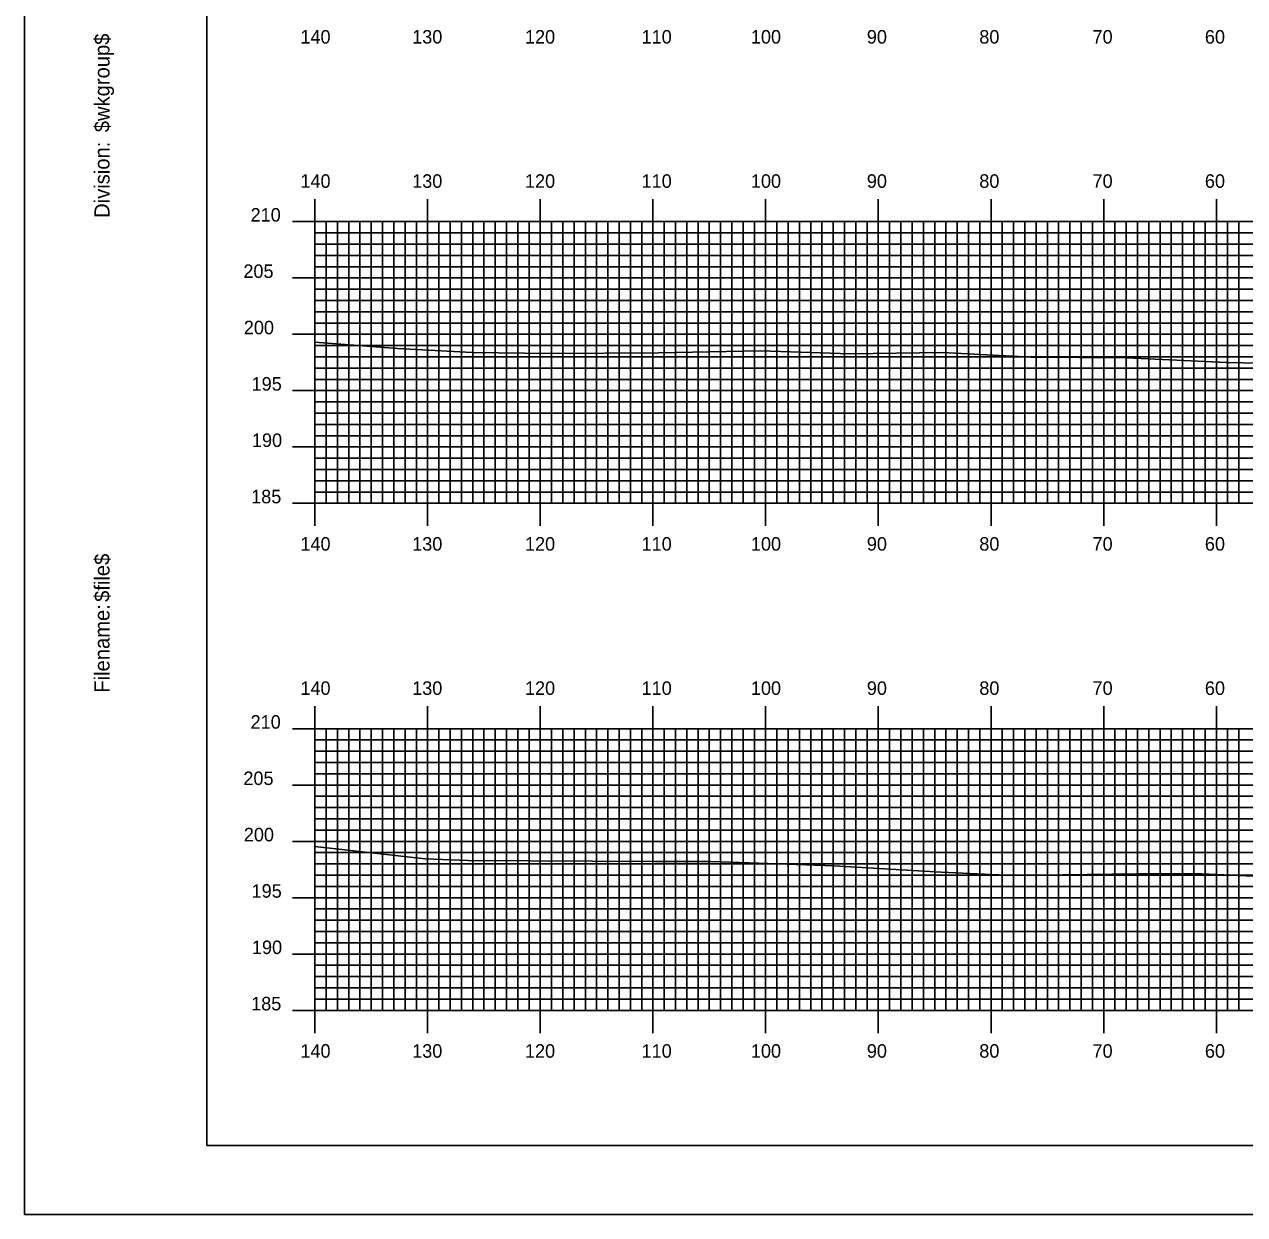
# Model space of a CAD drawing. Extents: x 1814128 to 1814471, y 442591 to 442811.
# Drawn here: x 1814128.2 to 1814236.5, y 442590.5 to 442696.2 of the extents above; entities that cross this region are included whole.
import ezdxf

# ---------------------------------------------------------------- set-up
doc = ezdxf.new("R2010")
doc.units = 0
for name, color, linetype in [('BORDER', 7, 'Continuous'), ('H_V ANNOTATION', 7, 'Continuous'), ('MAJOR', 7, 'Continuous'), ('MINOR', 7, 'Continuous'), ('PLOT BOUNDARY', 7, 'Continuous'), ('S_Roadway_Centerline', 7, 'Continuous')]:
    doc.layers.add(name, color=color, linetype=linetype)

msp = doc.modelspace()

# ---------------------------------------------------------------- linework, layer by layer
at = {"layer": 'BORDER'}
msp.add_lwpolyline([(1814144.39, 442596.67), (1814464.39, 442596.67), (1814464.39, 442806.67), (1814144.39, 442806.67)], close=True, dxfattribs=at)
at = {"layer": 'MAJOR'}
for p, q in [((1814153.99, 442680.67), (1814153.99, 442678.67)), ((1814163.99, 442680.67), (1814163.99, 442678.67)), ((1814173.99, 442680.67), (1814173.99, 442678.67)), ((1814183.99, 442680.67), (1814183.99, 442678.67)), ((1814193.99, 442680.67), (1814193.99, 442678.67)), ((1814203.99, 442680.67), (1814203.99, 442678.67)), ((1814213.99, 442680.67), (1814213.99, 442678.67)), ((1814223.99, 442680.67), (1814223.99, 442678.67)), ((1814233.99, 442680.67), (1814233.99, 442678.67)), ((1814151.99, 442678.67), (1814153.99, 442678.67)), ((1814153.99, 442678.67), (1814433.99, 442678.67)), ((1814153.99, 442653.67), (1814153.99, 442678.67)), ((1814153.99, 442653.67), (1814153.99, 442678.67)), ((1814153.99, 442678.67), (1814433.99, 442678.67)), ((1814163.99, 442653.67), (1814163.99, 442678.67)), ((1814173.99, 442653.67), (1814173.99, 442678.67)), ((1814183.99, 442653.67), (1814183.99, 442678.67)), ((1814193.99, 442653.67), (1814193.99, 442678.67)), ((1814203.99, 442653.67), (1814203.99, 442678.67)), ((1814213.99, 442653.67), (1814213.99, 442678.67)), ((1814223.99, 442653.67), (1814223.99, 442678.67)), ((1814233.99, 442653.67), (1814233.99, 442678.67)), ((1814151.99, 442673.67), (1814153.99, 442673.67)), ((1814153.99, 442673.67), (1814433.99, 442673.67)), ((1814151.99, 442668.67), (1814153.99, 442668.67)), ((1814153.99, 442668.67), (1814433.99, 442668.67)), ((1814151.99, 442663.67), (1814153.99, 442663.67)), ((1814153.99, 442663.67), (1814433.99, 442663.67)), ((1814151.99, 442658.67), (1814153.99, 442658.67)), ((1814153.99, 442658.67), (1814433.99, 442658.67)), ((1814151.99, 442653.67), (1814153.99, 442653.67)), ((1814153.99, 442653.67), (1814433.99, 442653.67)), ((1814153.99, 442653.67), (1814433.99, 442653.67)), ((1814153.99, 442651.66), (1814153.99, 442653.67)), ((1814163.99, 442651.66), (1814163.99, 442653.67)), ((1814173.99, 442651.66), (1814173.99, 442653.67)), ((1814183.99, 442651.66), (1814183.99, 442653.67)), ((1814193.99, 442651.66), (1814193.99, 442653.67)), ((1814203.99, 442651.66), (1814203.99, 442653.67)), ((1814213.99, 442651.66), (1814213.99, 442653.67)), ((1814223.99, 442651.66), (1814223.99, 442653.67)), ((1814233.99, 442651.66), (1814233.99, 442653.67)), ((1814153.99, 442635.67), (1814153.99, 442633.67)), ((1814163.99, 442635.67), (1814163.99, 442633.67)), ((1814173.99, 442635.67), (1814173.99, 442633.67)), ((1814183.99, 442635.67), (1814183.99, 442633.67)), ((1814193.99, 442635.67), (1814193.99, 442633.67)), ((1814203.99, 442635.67), (1814203.99, 442633.67)), ((1814213.99, 442635.67), (1814213.99, 442633.67)), ((1814223.99, 442635.67), (1814223.99, 442633.67)), ((1814233.99, 442635.67), (1814233.99, 442633.67)), ((1814151.99, 442633.67), (1814153.99, 442633.67)), ((1814153.99, 442633.67), (1814433.99, 442633.67)), ((1814153.99, 442608.67), (1814153.99, 442633.67)), ((1814153.99, 442608.67), (1814153.99, 442633.67)), ((1814153.99, 442633.67), (1814433.99, 442633.67)), ((1814163.99, 442608.67), (1814163.99, 442633.67)), ((1814173.99, 442608.67), (1814173.99, 442633.67)), ((1814183.99, 442608.67), (1814183.99, 442633.67)), ((1814193.99, 442608.67), (1814193.99, 442633.67)), ((1814203.99, 442608.67), (1814203.99, 442633.67)), ((1814213.99, 442608.67), (1814213.99, 442633.67)), ((1814223.99, 442608.67), (1814223.99, 442633.67)), ((1814233.99, 442608.67), (1814233.99, 442633.67)), ((1814151.99, 442628.67), (1814153.99, 442628.67)), ((1814153.99, 442628.67), (1814433.99, 442628.67)), ((1814151.99, 442623.67), (1814153.99, 442623.67)), ((1814153.99, 442623.67), (1814433.99, 442623.67)), ((1814151.99, 442618.67), (1814153.99, 442618.67)), ((1814153.99, 442618.67), (1814433.99, 442618.67)), ((1814151.99, 442613.67), (1814153.99, 442613.67)), ((1814153.99, 442613.67), (1814433.99, 442613.67)), ((1814151.99, 442608.67), (1814153.99, 442608.67)), ((1814153.99, 442608.67), (1814433.99, 442608.67)), ((1814153.99, 442608.67), (1814433.99, 442608.67)), ((1814153.99, 442606.66), (1814153.99, 442608.67)), ((1814163.99, 442606.66), (1814163.99, 442608.67)), ((1814173.99, 442606.66), (1814173.99, 442608.67)), ((1814183.99, 442606.66), (1814183.99, 442608.67)), ((1814193.99, 442606.66), (1814193.99, 442608.67)), ((1814203.99, 442606.66), (1814203.99, 442608.67)), ((1814213.99, 442606.66), (1814213.99, 442608.67)), ((1814223.99, 442606.66), (1814223.99, 442608.67)), ((1814233.99, 442606.66), (1814233.99, 442608.67))]:
    msp.add_line(p, q, dxfattribs=at)
at = {"layer": 'MINOR'}
for p, q in [((1814154.99, 442653.67), (1814154.99, 442678.67)), ((1814155.99, 442653.67), (1814155.99, 442678.67)), ((1814156.99, 442653.67), (1814156.99, 442678.67)), ((1814157.99, 442653.67), (1814157.99, 442678.67)), ((1814158.99, 442653.67), (1814158.99, 442678.67)), ((1814159.99, 442653.67), (1814159.99, 442678.67)), ((1814160.99, 442653.67), (1814160.99, 442678.67)), ((1814161.99, 442653.67), (1814161.99, 442678.67)), ((1814162.99, 442653.67), (1814162.99, 442678.67)), ((1814164.99, 442653.67), (1814164.99, 442678.67)), ((1814165.99, 442653.67), (1814165.99, 442678.67)), ((1814166.99, 442653.67), (1814166.99, 442678.67)), ((1814167.99, 442653.67), (1814167.99, 442678.67)), ((1814168.99, 442653.67), (1814168.99, 442678.67)), ((1814169.99, 442653.67), (1814169.99, 442678.67)), ((1814170.99, 442653.67), (1814170.99, 442678.67)), ((1814171.99, 442653.67), (1814171.99, 442678.67)), ((1814172.99, 442653.67), (1814172.99, 442678.67)), ((1814174.99, 442653.67), (1814174.99, 442678.67)), ((1814175.99, 442653.67), (1814175.99, 442678.67)), ((1814176.99, 442653.67), (1814176.99, 442678.67)), ((1814177.99, 442653.67), (1814177.99, 442678.67)), ((1814178.99, 442653.67), (1814178.99, 442678.67)), ((1814179.99, 442653.67), (1814179.99, 442678.67)), ((1814180.99, 442653.67), (1814180.99, 442678.67)), ((1814181.99, 442653.67), (1814181.99, 442678.67)), ((1814182.99, 442653.67), (1814182.99, 442678.67)), ((1814184.99, 442653.67), (1814184.99, 442678.67)), ((1814185.99, 442653.67), (1814185.99, 442678.67)), ((1814186.99, 442653.67), (1814186.99, 442678.67)), ((1814187.99, 442653.67), (1814187.99, 442678.67)), ((1814188.99, 442653.67), (1814188.99, 442678.67)), ((1814189.99, 442653.67), (1814189.99, 442678.67)), ((1814190.99, 442653.67), (1814190.99, 442678.67)), ((1814191.99, 442653.67), (1814191.99, 442678.67)), ((1814192.99, 442653.67), (1814192.99, 442678.67)), ((1814194.99, 442653.67), (1814194.99, 442678.67)), ((1814195.99, 442653.67), (1814195.99, 442678.67)), ((1814196.99, 442653.67), (1814196.99, 442678.67)), ((1814197.99, 442653.67), (1814197.99, 442678.67)), ((1814198.99, 442653.67), (1814198.99, 442678.67)), ((1814199.99, 442653.67), (1814199.99, 442678.67)), ((1814200.99, 442653.67), (1814200.99, 442678.67)), ((1814201.99, 442653.67), (1814201.99, 442678.67)), ((1814202.99, 442653.67), (1814202.99, 442678.67)), ((1814204.99, 442653.67), (1814204.99, 442678.67)), ((1814205.99, 442653.67), (1814205.99, 442678.67)), ((1814206.99, 442653.67), (1814206.99, 442678.67)), ((1814207.99, 442653.67), (1814207.99, 442678.67)), ((1814208.99, 442653.67), (1814208.99, 442678.67)), ((1814209.99, 442653.67), (1814209.99, 442678.67)), ((1814210.99, 442653.67), (1814210.99, 442678.67)), ((1814211.99, 442653.67), (1814211.99, 442678.67)), ((1814212.99, 442653.67), (1814212.99, 442678.67)), ((1814214.99, 442653.67), (1814214.99, 442678.67)), ((1814215.99, 442653.67), (1814215.99, 442678.67)), ((1814216.99, 442653.67), (1814216.99, 442678.67)), ((1814217.99, 442653.67), (1814217.99, 442678.67)), ((1814218.99, 442653.67), (1814218.99, 442678.67)), ((1814219.99, 442653.67), (1814219.99, 442678.67)), ((1814220.99, 442653.67), (1814220.99, 442678.67)), ((1814221.99, 442653.67), (1814221.99, 442678.67)), ((1814222.99, 442653.67), (1814222.99, 442678.67)), ((1814224.99, 442653.67), (1814224.99, 442678.67)), ((1814225.99, 442653.67), (1814225.99, 442678.67)), ((1814226.99, 442653.67), (1814226.99, 442678.67)), ((1814227.99, 442653.67), (1814227.99, 442678.67)), ((1814228.99, 442653.67), (1814228.99, 442678.67)), ((1814229.99, 442653.67), (1814229.99, 442678.67)), ((1814230.99, 442653.67), (1814230.99, 442678.67)), ((1814231.99, 442653.67), (1814231.99, 442678.67)), ((1814232.99, 442653.67), (1814232.99, 442678.67)), ((1814234.99, 442653.67), (1814234.99, 442678.67)), ((1814235.99, 442653.67), (1814235.99, 442678.67)), ((1814153.99, 442677.67), (1814433.99, 442677.67)), ((1814153.99, 442677.67), (1814156, 442677.67)), ((1814153.99, 442676.67), (1814433.99, 442676.67)), ((1814153.99, 442676.67), (1814156, 442676.67)), ((1814153.99, 442675.67), (1814433.99, 442675.67)), ((1814153.99, 442675.67), (1814156, 442675.67)), ((1814153.99, 442674.67), (1814433.99, 442674.67)), ((1814153.99, 442674.67), (1814156, 442674.67)), ((1814153.99, 442672.67), (1814433.99, 442672.67)), ((1814153.99, 442672.67), (1814156, 442672.67)), ((1814153.99, 442671.67), (1814433.99, 442671.67)), ((1814153.99, 442671.67), (1814156, 442671.67)), ((1814153.99, 442670.67), (1814433.99, 442670.67)), ((1814153.99, 442670.67), (1814156, 442670.67)), ((1814153.99, 442669.67), (1814433.99, 442669.67)), ((1814153.99, 442669.67), (1814156, 442669.67)), ((1814153.99, 442667.67), (1814433.99, 442667.67)), ((1814153.99, 442667.67), (1814156, 442667.67)), ((1814153.99, 442666.67), (1814433.99, 442666.67)), ((1814153.99, 442666.67), (1814156, 442666.67)), ((1814153.99, 442665.67), (1814433.99, 442665.67)), ((1814153.99, 442665.67), (1814156, 442665.67)), ((1814153.99, 442664.67), (1814433.99, 442664.67)), ((1814153.99, 442664.67), (1814156, 442664.67)), ((1814153.99, 442662.67), (1814433.99, 442662.67)), ((1814153.99, 442662.67), (1814156, 442662.67)), ((1814153.99, 442661.67), (1814433.99, 442661.67)), ((1814153.99, 442661.67), (1814156, 442661.67)), ((1814153.99, 442660.67), (1814433.99, 442660.67)), ((1814153.99, 442660.67), (1814156, 442660.67)), ((1814153.99, 442659.67), (1814433.99, 442659.67)), ((1814153.99, 442659.67), (1814156, 442659.67)), ((1814153.99, 442657.67), (1814433.99, 442657.67)), ((1814153.99, 442657.67), (1814156, 442657.67)), ((1814153.99, 442656.67), (1814433.99, 442656.67)), ((1814153.99, 442656.67), (1814156, 442656.67)), ((1814153.99, 442655.67), (1814433.99, 442655.67)), ((1814153.99, 442655.67), (1814156, 442655.67)), ((1814153.99, 442654.67), (1814433.99, 442654.67)), ((1814153.99, 442654.67), (1814156, 442654.67)), ((1814154.99, 442608.67), (1814154.99, 442633.67)), ((1814155.99, 442608.67), (1814155.99, 442633.67)), ((1814156.99, 442608.67), (1814156.99, 442633.67)), ((1814157.99, 442608.67), (1814157.99, 442633.67)), ((1814158.99, 442608.67), (1814158.99, 442633.67)), ((1814159.99, 442608.67), (1814159.99, 442633.67)), ((1814160.99, 442608.67), (1814160.99, 442633.67)), ((1814161.99, 442608.67), (1814161.99, 442633.67)), ((1814162.99, 442608.67), (1814162.99, 442633.67)), ((1814164.99, 442608.67), (1814164.99, 442633.67)), ((1814165.99, 442608.67), (1814165.99, 442633.67)), ((1814166.99, 442608.67), (1814166.99, 442633.67)), ((1814167.99, 442608.67), (1814167.99, 442633.67)), ((1814168.99, 442608.67), (1814168.99, 442633.67)), ((1814169.99, 442608.67), (1814169.99, 442633.67)), ((1814170.99, 442608.67), (1814170.99, 442633.67)), ((1814171.99, 442608.67), (1814171.99, 442633.67)), ((1814172.99, 442608.67), (1814172.99, 442633.67)), ((1814174.99, 442608.67), (1814174.99, 442633.67)), ((1814175.99, 442608.67), (1814175.99, 442633.67)), ((1814176.99, 442608.67), (1814176.99, 442633.67)), ((1814177.99, 442608.67), (1814177.99, 442633.67)), ((1814178.99, 442608.67), (1814178.99, 442633.67)), ((1814179.99, 442608.67), (1814179.99, 442633.67)), ((1814180.99, 442608.67), (1814180.99, 442633.67)), ((1814181.99, 442608.67), (1814181.99, 442633.67)), ((1814182.99, 442608.67), (1814182.99, 442633.67)), ((1814184.99, 442608.67), (1814184.99, 442633.67)), ((1814185.99, 442608.67), (1814185.99, 442633.67)), ((1814186.99, 442608.67), (1814186.99, 442633.67)), ((1814187.99, 442608.67), (1814187.99, 442633.67)), ((1814188.99, 442608.67), (1814188.99, 442633.67)), ((1814189.99, 442608.67), (1814189.99, 442633.67)), ((1814190.99, 442608.67), (1814190.99, 442633.67)), ((1814191.99, 442608.67), (1814191.99, 442633.67)), ((1814192.99, 442608.67), (1814192.99, 442633.67)), ((1814194.99, 442608.67), (1814194.99, 442633.67)), ((1814195.99, 442608.67), (1814195.99, 442633.67)), ((1814196.99, 442608.67), (1814196.99, 442633.67)), ((1814197.99, 442608.67), (1814197.99, 442633.67)), ((1814198.99, 442608.67), (1814198.99, 442633.67)), ((1814199.99, 442608.67), (1814199.99, 442633.67)), ((1814200.99, 442608.67), (1814200.99, 442633.67)), ((1814201.99, 442608.67), (1814201.99, 442633.67)), ((1814202.99, 442608.67), (1814202.99, 442633.67)), ((1814204.99, 442608.67), (1814204.99, 442633.67)), ((1814205.99, 442608.67), (1814205.99, 442633.67)), ((1814206.99, 442608.67), (1814206.99, 442633.67)), ((1814207.99, 442608.67), (1814207.99, 442633.67)), ((1814208.99, 442608.67), (1814208.99, 442633.67)), ((1814209.99, 442608.67), (1814209.99, 442633.67)), ((1814210.99, 442608.67), (1814210.99, 442633.67)), ((1814211.99, 442608.67), (1814211.99, 442633.67)), ((1814212.99, 442608.67), (1814212.99, 442633.67)), ((1814214.99, 442608.67), (1814214.99, 442633.67)), ((1814215.99, 442608.67), (1814215.99, 442633.67)), ((1814216.99, 442608.67), (1814216.99, 442633.67)), ((1814217.99, 442608.67), (1814217.99, 442633.67)), ((1814218.99, 442608.67), (1814218.99, 442633.67)), ((1814219.99, 442608.67), (1814219.99, 442633.67)), ((1814220.99, 442608.67), (1814220.99, 442633.67)), ((1814221.99, 442608.67), (1814221.99, 442633.67)), ((1814222.99, 442608.67), (1814222.99, 442633.67)), ((1814224.99, 442608.67), (1814224.99, 442633.67)), ((1814225.99, 442608.67), (1814225.99, 442633.67)), ((1814226.99, 442608.67), (1814226.99, 442633.67)), ((1814227.99, 442608.67), (1814227.99, 442633.67)), ((1814228.99, 442608.67), (1814228.99, 442633.67)), ((1814229.99, 442608.67), (1814229.99, 442633.67)), ((1814230.99, 442608.67), (1814230.99, 442633.67)), ((1814231.99, 442608.67), (1814231.99, 442633.67)), ((1814232.99, 442608.67), (1814232.99, 442633.67)), ((1814234.99, 442608.67), (1814234.99, 442633.67)), ((1814235.99, 442608.67), (1814235.99, 442633.67)), ((1814153.99, 442632.67), (1814433.99, 442632.67)), ((1814153.99, 442632.67), (1814156, 442632.67)), ((1814153.99, 442631.67), (1814433.99, 442631.67)), ((1814153.99, 442631.67), (1814156, 442631.67)), ((1814153.99, 442630.67), (1814433.99, 442630.67)), ((1814153.99, 442630.67), (1814156, 442630.67)), ((1814153.99, 442629.67), (1814433.99, 442629.67)), ((1814153.99, 442629.67), (1814156, 442629.67)), ((1814153.99, 442627.67), (1814433.99, 442627.67)), ((1814153.99, 442627.67), (1814156, 442627.67)), ((1814153.99, 442626.67), (1814433.99, 442626.67)), ((1814153.99, 442626.67), (1814156, 442626.67)), ((1814153.99, 442625.67), (1814433.99, 442625.67)), ((1814153.99, 442625.67), (1814156, 442625.67)), ((1814153.99, 442624.67), (1814433.99, 442624.67)), ((1814153.99, 442624.67), (1814156, 442624.67)), ((1814153.99, 442622.67), (1814433.99, 442622.67)), ((1814153.99, 442622.67), (1814156, 442622.67)), ((1814153.99, 442621.67), (1814433.99, 442621.67)), ((1814153.99, 442621.67), (1814156, 442621.67)), ((1814153.99, 442620.67), (1814433.99, 442620.67)), ((1814153.99, 442620.67), (1814156, 442620.67)), ((1814153.99, 442619.67), (1814433.99, 442619.67)), ((1814153.99, 442619.67), (1814156, 442619.67)), ((1814153.99, 442617.67), (1814433.99, 442617.67)), ((1814153.99, 442617.67), (1814156, 442617.67)), ((1814153.99, 442616.67), (1814433.99, 442616.67)), ((1814153.99, 442616.67), (1814156, 442616.67)), ((1814153.99, 442615.67), (1814433.99, 442615.67)), ((1814153.99, 442615.67), (1814156, 442615.67)), ((1814153.99, 442614.67), (1814433.99, 442614.67)), ((1814153.99, 442614.67), (1814156, 442614.67)), ((1814153.99, 442612.67), (1814433.99, 442612.67)), ((1814153.99, 442612.67), (1814156, 442612.67)), ((1814153.99, 442611.67), (1814433.99, 442611.67)), ((1814153.99, 442611.67), (1814156, 442611.67)), ((1814153.99, 442610.67), (1814433.99, 442610.67)), ((1814153.99, 442610.67), (1814156, 442610.67)), ((1814153.99, 442609.67), (1814433.99, 442609.67)), ((1814153.99, 442609.67), (1814156, 442609.67))]:
    msp.add_line(p, q, dxfattribs=at)
at = {"layer": 'PLOT BOUNDARY'}
msp.add_lwpolyline([(1814128.21, 442590.55), (1814468.21, 442590.55), (1814468.21, 442810.55), (1814128.21, 442810.55)], close=True, dxfattribs=at)
at = {"layer": 'S_Roadway_Centerline'}
for points in [[(1814153.99, 442667.97), (1814161.32, 442667.4), (1814167.95, 442667.05), (1814174.94, 442666.98), (1814184.48, 442667.03), (1814193.54, 442667.21), (1814201.48, 442666.94), (1814209.68, 442667.06), (1814217.54, 442666.63), (1814226.05, 442666.58), (1814234.88, 442666.16), (1814242.26, 442666.03), (1814250.37, 442665.6), (1814258.58, 442665.06), (1814275.22, 442664.27), (1814283.53, 442663.9), (1814291.88, 442664.37), (1814299.32, 442663.86), (1814308.93, 442663), (1814316.73, 442662.86), (1814325.57, 442662.36), (1814332.4, 442662.3), (1814342.63, 442662.38), (1814356.37, 442661.7)], [(1814153.99, 442623.21), (1814163.78, 442622.13), (1814167.6, 442621.98), (1814184.17, 442621.87), (1814189.15, 442621.88), (1814200.08, 442621.51), (1814209.56, 442620.94), (1814215.95, 442620.64), (1814226.91, 442620.8), (1814232.69, 442620.8), (1814239.23, 442620.49), (1814249.37, 442620.39), (1814258.43, 442619.91), (1814265.29, 442619.76), (1814273.95, 442619.48), (1814282.83, 442619.21), (1814297.29, 442618.7), (1814314.23, 442618.05), (1814320.92, 442617.59), (1814330.34, 442617.05), (1814337.24, 442616.72), (1814347.7, 442616.32)]]:
    msp.add_lwpolyline(points, dxfattribs=at)

# ---------------------------------------------------------------- texts
at = {"layer": 'BORDER'}
for s, p in [('$wkgroup$', (1814135.76, 442686.6)), ('Division:', (1814135.76, 442679)), ('$file$', (1814135.76, 442644.92)), ('Filename:', (1814135.76, 442636.86))]:
    msp.add_text(s, height=1.339, rotation=90, dxfattribs=at).set_placement(p)
at = {"layer": 'H_V ANNOTATION'}
for s, p in [('140', (1814152.7, 442694.47)), ('130', (1814162.62, 442694.47)), ('120', (1814172.63, 442694.47)), ('110', (1814182.98, 442694.47)), ('100', (1814192.68, 442694.47)), ('90', (1814202.97, 442694.47)), ('80', (1814212.95, 442694.47)), ('70', (1814223, 442694.47)), ('60', (1814232.97, 442694.47)), ('140', (1814152.7, 442681.67)), ('130', (1814162.62, 442681.67)), ('120', (1814172.63, 442681.67)), ('110', (1814182.98, 442681.67)), ('100', (1814192.68, 442681.67)), ('90', (1814202.97, 442681.67)), ('80', (1814212.95, 442681.67)), ('70', (1814223, 442681.67)), ('60', (1814232.97, 442681.67)), ('210', (1814148.28, 442678.67)), ('205', (1814147.64, 442673.67)), ('200', (1814147.68, 442668.67)), ('195', (1814148.37, 442663.67)), ('190', (1814148.4, 442658.67)), ('185', (1814148.33, 442653.67)), ('140', (1814152.7, 442649.47)), ('130', (1814162.62, 442649.47)), ('120', (1814172.63, 442649.47)), ('110', (1814182.98, 442649.47)), ('100', (1814192.68, 442649.47)), ('90', (1814202.97, 442649.47)), ('80', (1814212.95, 442649.47)), ('70', (1814223, 442649.47)), ('60', (1814232.97, 442649.47)), ('140', (1814152.7, 442636.67)), ('130', (1814162.62, 442636.67)), ('120', (1814172.63, 442636.67)), ('110', (1814182.98, 442636.67)), ('100', (1814192.68, 442636.67)), ('90', (1814202.97, 442636.67)), ('80', (1814212.95, 442636.67)), ('70', (1814223, 442636.67)), ('60', (1814232.97, 442636.67)), ('210', (1814148.28, 442633.67)), ('205', (1814147.64, 442628.67)), ('200', (1814147.68, 442623.67)), ('195', (1814148.37, 442618.67)), ('190', (1814148.4, 442613.67)), ('185', (1814148.33, 442608.67)), ('140', (1814152.7, 442604.47)), ('130', (1814162.62, 442604.47)), ('120', (1814172.63, 442604.47)), ('110', (1814182.98, 442604.47)), ('100', (1814192.68, 442604.47)), ('90', (1814202.97, 442604.47)), ('80', (1814212.95, 442604.47)), ('70', (1814223, 442604.47)), ('60', (1814232.97, 442604.47))]:
    msp.add_text(s, height=1.2, dxfattribs=at).set_placement(p)
at = {"layer": 'MAJOR'}
for p in [(1814153.99, 442653.67), (1814153.99, 442608.67)]:
    msp.add_text('-', height=0.012, dxfattribs=at).set_placement(p)

doc.saveas('drawing.dxf')
